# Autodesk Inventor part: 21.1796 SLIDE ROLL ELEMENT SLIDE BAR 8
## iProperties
Created: 2007-05
Part Number: 21.1796 SLIDE ROLL ELEMENT SLIDE BAR 8
Material: UHMW, Black
Document SubType Name: Modeling
Designer: Andy Moles
Density: 0.94 g/cm^3
Mass: 21.4598 g
Surface Area: 97.8602 cm^2
Volume: 22.8296 cm^3
Author: Andy Moles
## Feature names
1. Extrusion1
2. Extrusion5
3. Hole1
4. Extrusion6
5. Mirror2
